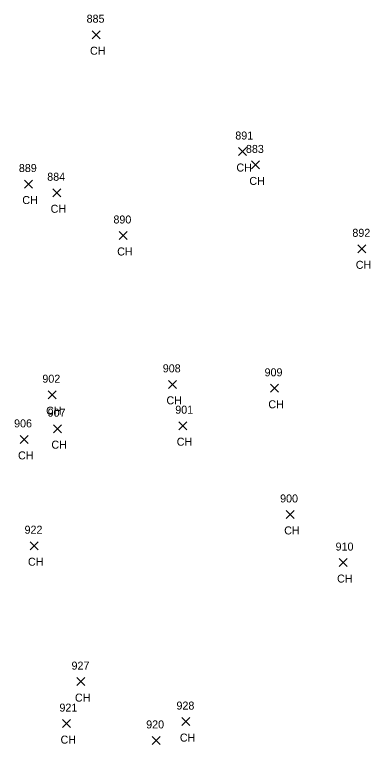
# Model space of a CAD drawing. Extents: x 1885914 to 1887218, y 756253 to 760620.
# Drawn here: x 1886653.2 to 1886742.1, y 759764.6 to 759947 of the extents above; entities that cross this region are included whole.
import ezdxf

# ---------------------------------------------------------------- set-up
doc = ezdxf.new("R2010")
doc.units = 0
for name, color, linetype in [('L_A', 7, 'Continuous'), ('L_I', 7, 'Continuous'), ('L_TIC', 7, 'Continuous')]:
    doc.layers.add(name, color=color, linetype=linetype)

msp = doc.modelspace()

# ---------------------------------------------------------------- linework, layer by layer
at = {"layer": 'L_TIC'}
for points in [[(1886672.57, 759940.97), (1886674.57, 759942.97)], [(1886674.57, 759940.97), (1886672.57, 759942.97)], [(1886709.14, 759911.77), (1886711.14, 759913.77)], [(1886711.14, 759911.77), (1886709.14, 759913.77)], [(1886712.36, 759908.42), (1886714.36, 759910.42)], [(1886714.36, 759908.42), (1886712.36, 759910.42)], [(1886655.67, 759903.64), (1886657.67, 759905.64)], [(1886657.67, 759903.64), (1886655.67, 759905.64)], [(1886662.75, 759901.46), (1886664.75, 759903.46)], [(1886664.75, 759901.46), (1886662.75, 759903.46)], [(1886679.36, 759890.78), (1886681.36, 759892.78)], [(1886681.36, 759890.78), (1886679.36, 759892.78)], [(1886738.93, 759887.45), (1886740.93, 759889.45)], [(1886740.93, 759887.45), (1886738.93, 759889.45)], [(1886691.67, 759853.57), (1886693.67, 759855.57)], [(1886693.67, 759853.57), (1886691.67, 759855.57)], [(1886717.1, 759852.58), (1886719.1, 759854.58)], [(1886719.1, 759852.58), (1886717.1, 759854.58)], [(1886661.61, 759850.98), (1886663.61, 759852.98)], [(1886663.61, 759850.98), (1886661.61, 759852.98)], [(1886662.94, 759842.49), (1886664.94, 759844.49)], [(1886664.94, 759842.49), (1886662.94, 759844.49)], [(1886694.22, 759843.23), (1886696.22, 759845.23)], [(1886696.22, 759843.23), (1886694.22, 759845.23)], [(1886654.61, 759839.81), (1886656.61, 759841.81)], [(1886656.61, 759839.81), (1886654.61, 759841.81)], [(1886721.06, 759821.05), (1886723.06, 759823.05)], [(1886723.06, 759821.05), (1886721.06, 759823.05)], [(1886657.08, 759813.23), (1886659.08, 759815.23)], [(1886659.08, 759813.23), (1886657.08, 759815.23)], [(1886734.26, 759809.02), (1886736.26, 759811.02)], [(1886736.26, 759809.02), (1886734.26, 759811.02)], [(1886668.81, 759779.26), (1886670.81, 759781.26)], [(1886670.81, 759779.26), (1886668.81, 759781.26)], [(1886695.01, 759769.27), (1886697.01, 759771.27)], [(1886697.01, 759769.27), (1886695.01, 759771.27)], [(1886665.22, 759768.76), (1886667.22, 759770.76)], [(1886667.22, 759768.76), (1886665.22, 759770.76)], [(1886687.54, 759764.56), (1886689.54, 759766.56)], [(1886689.54, 759764.56), (1886687.54, 759766.56)]]:
    msp.add_lwpolyline(points, dxfattribs=at)

# ---------------------------------------------------------------- texts
at = {"layer": 'L_A'}
for p in [(1886672.06, 759936.97), (1886708.62, 759907.77), (1886711.85, 759904.42), (1886655.16, 759899.64), (1886662.23, 759897.46), (1886678.85, 759886.78), (1886738.42, 759883.45), (1886691.15, 759849.57), (1886716.59, 759848.58), (1886661.1, 759846.98), (1886662.42, 759838.49), (1886693.71, 759839.23), (1886654.1, 759835.81), (1886720.55, 759817.05), (1886656.57, 759809.23), (1886733.75, 759805.02), (1886668.3, 759775.26), (1886664.71, 759764.76), (1886694.5, 759765.27)]:
    msp.add_text('CH', height=2, dxfattribs=at).set_placement(p)
at = {"layer": 'L_I'}
for s, p in [('885', (1886671.21, 759944.97)), ('891', (1886708.34, 759915.77)), ('883', (1886711, 759912.42)), ('889', (1886654.3, 759907.64)), ('884', (1886661.38, 759905.46)), ('890', (1886677.91, 759894.78)), ('892', (1886737.57, 759891.45)), ('908', (1886690.23, 759857.57)), ('902', (1886660.17, 759854.98)), ('909', (1886715.65, 759856.58)), ('907', (1886661.49, 759846.49)), ('901', (1886693.35, 759847.23)), ('906', (1886653.11, 759843.81)), ('900', (1886719.53, 759825.05)), ('922', (1886655.72, 759817.23)), ('910', (1886733.38, 759813.02)), ('927', (1886667.45, 759783.26)), ('921', (1886664.43, 759772.76)), ('928', (1886693.65, 759773.27)), ('920', (1886686.09, 759768.56))]:
    msp.add_text(s, height=2, dxfattribs=at).set_placement(p)

doc.saveas('drawing.dxf')
